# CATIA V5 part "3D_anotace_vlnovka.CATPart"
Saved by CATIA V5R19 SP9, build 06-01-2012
Part number: Part115
Bounding box of the stored display mesh (mm): x -26.778 to 26.778, y -26.687 to 26.687, z 0 to 20
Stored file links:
  C:\Profiles\jmaur82\Desktop\3D_anotace_vlnovka.CATPart
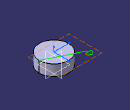
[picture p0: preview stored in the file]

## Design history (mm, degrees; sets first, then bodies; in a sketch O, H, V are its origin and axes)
TTRSSet1
f4a2d38f3ddc11d3a929006094b99c4b_11 "CATTPSSet"
Body1 (main body)
  Sketch1 on xy-plane, origin (0, 0, 0), H (1, 0, 0), V (0, 1, 0)
    circle A1 centre (0, 0) radius 26.7782
    radius A1 = 26.7782
  Pad1: profile Sketch1, direction (0, 0, 1), length 20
